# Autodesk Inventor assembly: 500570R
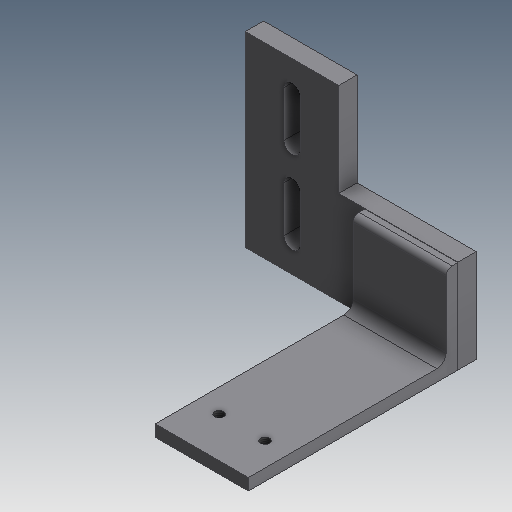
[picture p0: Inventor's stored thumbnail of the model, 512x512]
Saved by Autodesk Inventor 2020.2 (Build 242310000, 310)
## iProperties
Created: 2000-02
Part Number: 500570R
Description: WMT-FA,AH,CP,PLATE,MNT,PLOW
Document SubType Name: Assembly
Designer: sspink
Mass: 1022.11 g
Surface Area: 405.423 cm^2
Volume: 130.538 cm^3
Density: 7.83 g/cm^3
Control State: 0
Checked Out: False
Master: False
Shininess: 0.0
Length Units: 11269
Angle Units: 11279
Time Units: 11290
Mass Units: 11283
Length Display Precision: 3
Angle Display Precision: 2
Compacted: True
Dimensions: 102x124,3x116 mm
Mass: 1,022 kg
Density: 0.0
Volumn: 0.0
Area: 0.0
PropertySet Name: Model Information
Author: sspink
Revision Number: -
Title: WMT-FA,AH,CP,PLATE,MNT,PLOW
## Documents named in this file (3)
- D:\07 - DEMODATEN\OTX 2019 - Dataset - UPDATE - Dez2019\Designs\07-Packing machine\500570R.iam
- D:\07 - DEMODATEN\OTX 2019 - Dataset - UPDATE - Dez2019\Designs\07-Packing machine\Parts\ADSK-011500.ipt
- D:\07 - DEMODATEN\OTX 2019 - Dataset - UPDATE - Dez2019\Designs\07-Packing machine\Parts\ADSK-011501.ipt
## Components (2 placed, 2 different names)
1. ADSK-011500:1 — Mate:1, Flush:1, Flush:2
2. ADSK-011501:1 — Mate:1, Flush:1, Flush:2
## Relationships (3: Flush 2, Mate 1)
- Mate:1: ADSK-011500:1 ↔ ADSK-011501:1
- Flush:1: ADSK-011500:1 ↔ ADSK-011501:1
- Flush:2: ADSK-011500:1 ↔ ADSK-011501:1
